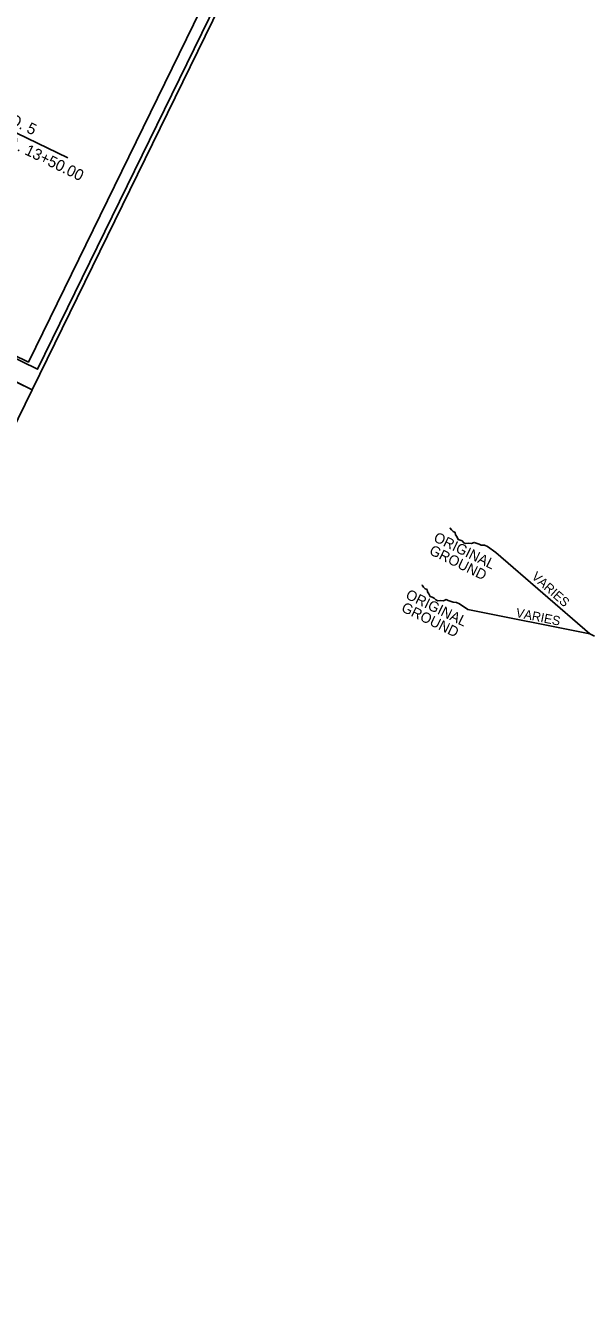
# Model space of a CAD drawing. Extents: x 1518247 to 1523638, y 635234 to 639927.
# Drawn here: x 1521464 to 1522079, y 635234 to 636619 of the extents above; entities that cross this region are included whole.
import ezdxf

# ---------------------------------------------------------------- set-up
doc = ezdxf.new("R2010")
doc.units = 0
for name, color, linetype in [('Default', 7, 'Continuous'), ('Sheet Cutting Line CELL', 7, 'Continuous'), ('Sheet Plot Border Inside CELL', 7, 'Continuous'), ('Sheet Plot Border Outside CELL', 7, 'Continuous'), ('Sheet Typical CELL', 7, 'Continuous'), ('Typical Berm CELL', 7, 'Continuous'), ('Typical Hinge Slope Arterial CELL', 7, 'Continuous'), ('Typical Hinge Slope Interstate CELL', 7, 'Continuous'), ('Typical Pavement Slope CELL', 7, 'Continuous'), ('Typical Text Label CELL', 7, 'Continuous')]:
    doc.layers.add(name, color=color, linetype=linetype)

msp = doc.modelspace()

# ---------------------------------------------------------------- linework, layer by layer
at = {"layer": 'Default'}
msp.add_lwpolyline([(1521471.5, 636222.3), (1519958.7, 636962.2), (1520442, 637950.3), (1521954.7, 637210.5)], close=True, dxfattribs=at)
at = {"layer": 'Sheet Cutting Line CELL'}
for p, q in [((1519958.7, 636962.2), (1521471.5, 636222.3)), ((1521471.5, 636222.3), (1519958.7, 636962.2))]:
    msp.add_line(p, q, dxfattribs=at)
at = {"layer": 'Sheet Plot Border Inside CELL'}
msp.add_lwpolyline([(1521940.8, 637192.3), (1520443.8, 637924.5), (1519980.2, 636976.6), (1521477.3, 636244.5)], close=True, dxfattribs=at)
at = {"layer": 'Sheet Plot Border Outside CELL'}
for points in [[(1521954.7, 637210.5), (1520442, 637950.3), (1519958.7, 636962.2), (1521471.5, 636222.3)], [(1521471.5, 636222.3), (1519958.7, 636962.2), (1519475.4, 635974), (1520988.2, 635234.2)]]:
    msp.add_lwpolyline(points, close=True, dxfattribs=at)
at = {"layer": 'Sheet Typical CELL'}
msp.add_lwpolyline([(1521928.5, 637195.5), (1520581, 637854.5), (1520119.7, 636911.3), (1521467.2, 636252.3)], close=True, dxfattribs=at)
at = {"layer": 'Typical Berm CELL'}
msp.add_line((1522083.7, 635954), (1522078.5, 635956.6), dxfattribs=at)
at = {"layer": 'Typical Hinge Slope Interstate CELL'}
for q in [(1521976.2, 636045.2), (1521945.8, 635983)]:
    msp.add_line((1522078.5, 635956.6), q, dxfattribs=at)
for points in [[(1521976.2, 636045.2), (1521967.2, 636051.6), (1521963.9, 636052.9), (1521960.3, 636053.1), (1521958.1, 636054), (1521954.9, 636055.3), (1521952.7, 636056.1), (1521949.7, 636054.8), (1521946, 636055.1), (1521943.4, 636054.8), (1521941.3, 636055.7), (1521939.5, 636057.7), (1521937.4, 636058.5), (1521935.2, 636059.4), (1521933.9, 636062.4), (1521932.2, 636064.4), (1521932, 636067), (1521929.8, 636067.8), (1521928.1, 636069.8), (1521926.4, 636071.7), (1521926.3, 636071.8)], [(1521945.8, 635983), (1521936.7, 635989.3), (1521933.5, 635990.6), (1521929.8, 635990.9), (1521927.7, 635991.7), (1521924.4, 635993), (1521922.3, 635993.9), (1521919.2, 635992.6), (1521915.6, 635992.8), (1521913, 635992.6), (1521910.8, 635993.5), (1521909.1, 635995.4), (1521906.9, 635996.3), (1521904.8, 635997.1), (1521903.5, 636000.2), (1521901.8, 636002.1), (1521901.5, 636004.7), (1521899.4, 636005.6), (1521897.7, 636007.5), (1521895.9, 636009.5), (1521895.8, 636009.6)]]:
    msp.add_lwpolyline(points, dxfattribs=at)
at = {"layer": 'Typical Text Label CELL'}
msp.add_line((1521256.1, 636598.1), (1521510.1, 636474.5), dxfattribs=at)

# ---------------------------------------------------------------- texts
at = {"layer": 'Typical Hinge Slope Arterial CELL'}
for rotation, p in [(318.3142, (1522014.5, 636017.6)), (348.6711, (1521997.5, 635975))]:
    msp.add_text('VARIES', height=9.97, rotation=rotation, dxfattribs=at).set_placement(p)
at = {"layer": 'Typical Hinge Slope Interstate CELL'}
for s, p in [('ORIGINAL', (1521907.6, 636057.8)), ('GROUND', (1521902.9, 636043.7)), ('ORIGINAL', (1521877.2, 635995.5)), ('GROUND', (1521872.5, 635981.5))]:
    msp.add_text(s, height=11.21, rotation=334.0511, dxfattribs=at).set_placement(p)
at = {"layer": 'Typical Pavement Slope CELL'}
msp.add_text('-LPC- STA. 10+75.53 to -LPC- STA. 13+50.00', height=12.164, rotation=334.0511, dxfattribs=at).set_placement((1521222.9, 636595.4))
at = {"layer": 'Typical Text Label CELL'}
msp.add_text('USE TYPICAL SECTION NO. 5', height=12.164, rotation=334.0511, dxfattribs=at).set_placement((1521266, 636599.4))

doc.saveas('drawing.dxf')
